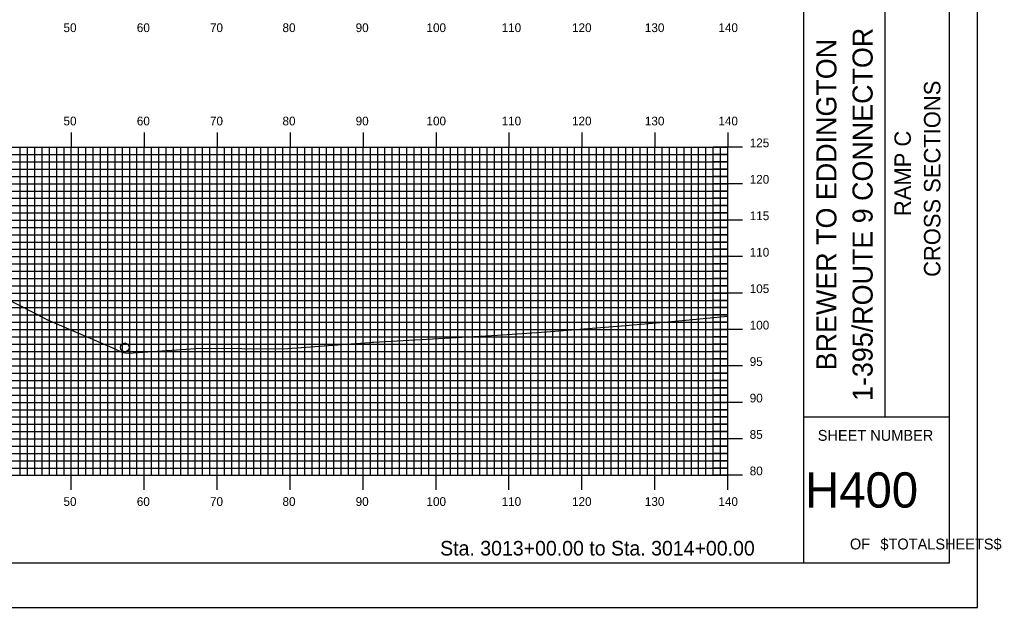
# Model space of a CAD drawing. Extents: x 1684405 to 1684749, y 461260 to 461480.
# Drawn here: x 1684614.1 to 1684748.7, y 461260 to 461340.6 of the extents above; entities that cross this region are included whole.
import ezdxf

# ---------------------------------------------------------------- set-up
doc = ezdxf.new("R2010")
doc.units = 0
for name, color, linetype in [('BORDER', 7, 'Continuous'), ('H_V ANNOTATION', 7, 'Continuous'), ('MAJOR', 7, 'Continuous'), ('MINOR', 7, 'Continuous'), ('PLOT BOUNDARY', 7, 'Continuous'), ('S_Drainage_Invert', 7, 'Continuous'), ('S_Roadway_Centerline', 7, 'Continuous')]:
    doc.layers.add(name, color=color, linetype=linetype)

msp = doc.modelspace()

# ---------------------------------------------------------------- linework, layer by layer
at = {"layer": 'BORDER'}
for p, q in [((1684721.6, 461266.07), (1684721.6, 461476.07)), ((1684732.79, 461286.08), (1684732.79, 461356.08)), ((1684721.6, 461286.08), (1684741.6, 461286.08))]:
    msp.add_line(p, q, dxfattribs=at)
msp.add_lwpolyline([(1684421.6, 461266.07), (1684741.6, 461266.07), (1684741.6, 461476.07), (1684421.6, 461476.07)], close=True, dxfattribs=at)
at = {"layer": 'MAJOR'}
for p, q in [((1684621.2, 461325.08), (1684621.2, 461323.07)), ((1684631.2, 461325.08), (1684631.2, 461323.07)), ((1684641.2, 461325.08), (1684641.2, 461323.07)), ((1684651.2, 461325.08), (1684651.2, 461323.07)), ((1684661.2, 461325.08), (1684661.2, 461323.07)), ((1684671.2, 461325.08), (1684671.2, 461323.07)), ((1684681.2, 461325.08), (1684681.2, 461323.07)), ((1684691.2, 461325.08), (1684691.2, 461323.07)), ((1684701.2, 461325.08), (1684701.2, 461323.07)), ((1684711.2, 461325.08), (1684711.2, 461323.07)), ((1684431.2, 461323.07), (1684711.2, 461323.07)), ((1684431.2, 461323.07), (1684711.2, 461323.07)), ((1684621.2, 461278.07), (1684621.2, 461323.07)), ((1684631.2, 461278.07), (1684631.2, 461323.07)), ((1684641.2, 461278.07), (1684641.2, 461323.07)), ((1684651.2, 461278.07), (1684651.2, 461323.07)), ((1684661.2, 461278.07), (1684661.2, 461323.07)), ((1684671.2, 461278.07), (1684671.2, 461323.07)), ((1684681.2, 461278.07), (1684681.2, 461323.07)), ((1684691.2, 461278.07), (1684691.2, 461323.07)), ((1684701.2, 461278.07), (1684701.2, 461323.07)), ((1684713.21, 461323.07), (1684709.2, 461323.07)), ((1684711.2, 461278.07), (1684711.2, 461323.07)), ((1684711.2, 461278.07), (1684711.2, 461323.07)), ((1684431.2, 461318.07), (1684711.2, 461318.07)), ((1684713.21, 461318.07), (1684709.2, 461318.07)), ((1684431.2, 461313.07), (1684711.2, 461313.07)), ((1684713.21, 461313.07), (1684709.2, 461313.07)), ((1684431.2, 461308.07), (1684711.2, 461308.07)), ((1684713.21, 461308.07), (1684709.2, 461308.07)), ((1684431.2, 461303.07), (1684711.2, 461303.07)), ((1684713.21, 461303.07), (1684709.2, 461303.07)), ((1684431.2, 461298.07), (1684711.2, 461298.07)), ((1684713.21, 461298.07), (1684709.2, 461298.07)), ((1684431.2, 461293.07), (1684711.2, 461293.07)), ((1684713.21, 461293.07), (1684709.2, 461293.07)), ((1684431.2, 461288.07), (1684711.2, 461288.07)), ((1684713.21, 461288.07), (1684709.2, 461288.07)), ((1684431.2, 461283.07), (1684711.2, 461283.07)), ((1684713.21, 461283.07), (1684709.2, 461283.07)), ((1684431.2, 461278.07), (1684711.2, 461278.07)), ((1684431.2, 461278.07), (1684711.2, 461278.07)), ((1684621.2, 461276.07), (1684621.2, 461278.07)), ((1684631.2, 461276.07), (1684631.2, 461278.07)), ((1684641.2, 461276.07), (1684641.2, 461278.07)), ((1684651.2, 461276.07), (1684651.2, 461278.07)), ((1684661.2, 461276.07), (1684661.2, 461278.07)), ((1684671.2, 461276.07), (1684671.2, 461278.07)), ((1684681.2, 461276.07), (1684681.2, 461278.07)), ((1684691.2, 461276.07), (1684691.2, 461278.07)), ((1684701.2, 461276.07), (1684701.2, 461278.07)), ((1684713.21, 461278.07), (1684709.2, 461278.07)), ((1684711.2, 461276.07), (1684711.2, 461278.07))]:
    msp.add_line(p, q, dxfattribs=at)
at = {"layer": 'MINOR'}
for p, q in [((1684431.2, 461322.07), (1684711.2, 461322.07)), ((1684614.2, 461278.07), (1684614.2, 461323.07)), ((1684615.2, 461278.07), (1684615.2, 461323.07)), ((1684616.2, 461278.07), (1684616.2, 461323.07)), ((1684617.2, 461278.07), (1684617.2, 461323.07)), ((1684618.2, 461278.07), (1684618.2, 461323.07)), ((1684619.2, 461278.07), (1684619.2, 461323.07)), ((1684620.2, 461278.07), (1684620.2, 461323.07)), ((1684622.2, 461278.07), (1684622.2, 461323.07)), ((1684623.2, 461278.07), (1684623.2, 461323.07)), ((1684624.2, 461278.07), (1684624.2, 461323.07)), ((1684625.2, 461278.07), (1684625.2, 461323.07)), ((1684626.2, 461278.07), (1684626.2, 461323.07)), ((1684627.2, 461278.07), (1684627.2, 461323.07)), ((1684628.2, 461278.07), (1684628.2, 461323.07)), ((1684629.2, 461278.07), (1684629.2, 461323.07)), ((1684630.2, 461278.07), (1684630.2, 461323.07)), ((1684632.2, 461278.07), (1684632.2, 461323.07)), ((1684633.2, 461278.07), (1684633.2, 461323.07)), ((1684634.2, 461278.07), (1684634.2, 461323.07)), ((1684635.2, 461278.07), (1684635.2, 461323.07)), ((1684636.2, 461278.07), (1684636.2, 461323.07)), ((1684637.2, 461278.07), (1684637.2, 461323.07)), ((1684638.2, 461278.07), (1684638.2, 461323.07)), ((1684639.2, 461278.07), (1684639.2, 461323.07)), ((1684640.2, 461278.07), (1684640.2, 461323.07)), ((1684642.2, 461278.07), (1684642.2, 461323.07)), ((1684643.2, 461278.07), (1684643.2, 461323.07)), ((1684644.2, 461278.07), (1684644.2, 461323.07)), ((1684645.2, 461278.07), (1684645.2, 461323.07)), ((1684646.2, 461278.07), (1684646.2, 461323.07)), ((1684647.2, 461278.07), (1684647.2, 461323.07)), ((1684648.2, 461278.07), (1684648.2, 461323.07)), ((1684649.2, 461278.07), (1684649.2, 461323.07)), ((1684650.2, 461278.07), (1684650.2, 461323.07)), ((1684652.2, 461278.07), (1684652.2, 461323.07)), ((1684653.2, 461278.07), (1684653.2, 461323.07)), ((1684654.2, 461278.07), (1684654.2, 461323.07)), ((1684655.2, 461278.07), (1684655.2, 461323.07)), ((1684656.2, 461278.07), (1684656.2, 461323.07)), ((1684657.2, 461278.07), (1684657.2, 461323.07)), ((1684658.2, 461278.07), (1684658.2, 461323.07)), ((1684659.2, 461278.07), (1684659.2, 461323.07)), ((1684660.2, 461278.07), (1684660.2, 461323.07)), ((1684662.2, 461278.07), (1684662.2, 461323.07)), ((1684663.2, 461278.07), (1684663.2, 461323.07)), ((1684664.2, 461278.07), (1684664.2, 461323.07)), ((1684665.2, 461278.07), (1684665.2, 461323.07)), ((1684666.2, 461278.07), (1684666.2, 461323.07)), ((1684667.2, 461278.07), (1684667.2, 461323.07)), ((1684668.2, 461278.07), (1684668.2, 461323.07)), ((1684669.2, 461278.07), (1684669.2, 461323.07)), ((1684670.2, 461278.07), (1684670.2, 461323.07)), ((1684672.2, 461278.07), (1684672.2, 461323.07)), ((1684673.2, 461278.07), (1684673.2, 461323.07)), ((1684674.2, 461278.07), (1684674.2, 461323.07)), ((1684675.2, 461278.07), (1684675.2, 461323.07)), ((1684676.2, 461278.07), (1684676.2, 461323.07)), ((1684677.2, 461278.07), (1684677.2, 461323.07)), ((1684678.2, 461278.07), (1684678.2, 461323.07)), ((1684679.2, 461278.07), (1684679.2, 461323.07)), ((1684680.2, 461278.07), (1684680.2, 461323.07)), ((1684682.2, 461278.07), (1684682.2, 461323.07)), ((1684683.2, 461278.07), (1684683.2, 461323.07)), ((1684684.2, 461278.07), (1684684.2, 461323.07)), ((1684685.2, 461278.07), (1684685.2, 461323.07)), ((1684686.2, 461278.07), (1684686.2, 461323.07)), ((1684687.2, 461278.07), (1684687.2, 461323.07)), ((1684688.2, 461278.07), (1684688.2, 461323.07)), ((1684689.2, 461278.07), (1684689.2, 461323.07)), ((1684690.2, 461278.07), (1684690.2, 461323.07)), ((1684692.2, 461278.07), (1684692.2, 461323.07)), ((1684693.2, 461278.07), (1684693.2, 461323.07)), ((1684694.2, 461278.07), (1684694.2, 461323.07)), ((1684695.2, 461278.07), (1684695.2, 461323.07)), ((1684696.2, 461278.07), (1684696.2, 461323.07)), ((1684697.2, 461278.07), (1684697.2, 461323.07)), ((1684698.2, 461278.07), (1684698.2, 461323.07)), ((1684699.2, 461278.07), (1684699.2, 461323.07)), ((1684700.2, 461278.07), (1684700.2, 461323.07)), ((1684702.2, 461278.07), (1684702.2, 461323.07)), ((1684703.2, 461278.07), (1684703.2, 461323.07)), ((1684704.2, 461278.07), (1684704.2, 461323.07)), ((1684705.2, 461278.07), (1684705.2, 461323.07)), ((1684706.2, 461278.07), (1684706.2, 461323.07)), ((1684707.2, 461278.07), (1684707.2, 461323.07)), ((1684708.2, 461278.07), (1684708.2, 461323.07)), ((1684709.2, 461278.07), (1684709.2, 461323.07)), ((1684711.2, 461322.07), (1684709.2, 461322.07)), ((1684710.2, 461278.07), (1684710.2, 461323.07)), ((1684431.2, 461321.07), (1684711.2, 461321.07)), ((1684711.2, 461321.07), (1684709.2, 461321.07)), ((1684431.2, 461320.07), (1684711.2, 461320.07)), ((1684431.2, 461319.07), (1684711.2, 461319.07)), ((1684711.2, 461320.07), (1684709.2, 461320.07)), ((1684711.2, 461319.07), (1684709.2, 461319.07)), ((1684431.2, 461317.07), (1684711.2, 461317.07)), ((1684711.2, 461317.07), (1684709.2, 461317.07)), ((1684431.2, 461316.07), (1684711.2, 461316.07)), ((1684431.2, 461315.07), (1684711.2, 461315.07)), ((1684711.2, 461316.07), (1684709.2, 461316.07)), ((1684711.2, 461315.07), (1684709.2, 461315.07)), ((1684431.2, 461314.07), (1684711.2, 461314.07)), ((1684711.2, 461314.07), (1684709.2, 461314.07)), ((1684431.2, 461312.07), (1684711.2, 461312.07)), ((1684431.2, 461311.07), (1684711.2, 461311.07)), ((1684711.2, 461312.07), (1684709.2, 461312.07)), ((1684711.2, 461311.07), (1684709.2, 461311.07)), ((1684431.2, 461310.07), (1684711.2, 461310.07)), ((1684711.2, 461310.07), (1684709.2, 461310.07)), ((1684431.2, 461309.07), (1684711.2, 461309.07)), ((1684711.2, 461309.07), (1684709.2, 461309.07)), ((1684431.2, 461307.07), (1684711.2, 461307.07)), ((1684711.2, 461307.07), (1684709.2, 461307.07)), ((1684431.2, 461306.07), (1684711.2, 461306.07)), ((1684711.2, 461306.07), (1684709.2, 461306.07)), ((1684431.2, 461305.07), (1684711.2, 461305.07)), ((1684711.2, 461305.07), (1684709.2, 461305.07)), ((1684431.2, 461304.07), (1684711.2, 461304.07)), ((1684711.2, 461304.07), (1684709.2, 461304.07)), ((1684431.2, 461302.07), (1684711.2, 461302.07)), ((1684711.2, 461302.07), (1684709.2, 461302.07)), ((1684431.2, 461301.07), (1684711.2, 461301.07)), ((1684711.2, 461301.07), (1684709.2, 461301.07)), ((1684431.2, 461300.07), (1684711.2, 461300.07)), ((1684431.2, 461299.07), (1684711.2, 461299.07)), ((1684711.2, 461300.07), (1684709.2, 461300.07)), ((1684711.2, 461299.07), (1684709.2, 461299.07)), ((1684431.2, 461297.07), (1684711.2, 461297.07)), ((1684711.2, 461297.07), (1684709.2, 461297.07)), ((1684431.2, 461296.07), (1684711.2, 461296.07)), ((1684431.2, 461295.07), (1684711.2, 461295.07)), ((1684711.2, 461296.07), (1684709.2, 461296.07)), ((1684711.2, 461295.07), (1684709.2, 461295.07)), ((1684431.2, 461294.07), (1684711.2, 461294.07)), ((1684711.2, 461294.07), (1684709.2, 461294.07)), ((1684431.2, 461292.07), (1684711.2, 461292.07)), ((1684431.2, 461291.07), (1684711.2, 461291.07)), ((1684711.2, 461292.07), (1684709.2, 461292.07)), ((1684711.2, 461291.07), (1684709.2, 461291.07)), ((1684431.2, 461290.07), (1684711.2, 461290.07)), ((1684711.2, 461290.07), (1684709.2, 461290.07)), ((1684431.2, 461289.07), (1684711.2, 461289.07)), ((1684711.2, 461289.07), (1684709.2, 461289.07)), ((1684431.2, 461287.07), (1684711.2, 461287.07)), ((1684711.2, 461287.07), (1684709.2, 461287.07)), ((1684431.2, 461286.07), (1684711.2, 461286.07)), ((1684711.2, 461286.07), (1684709.2, 461286.07)), ((1684431.2, 461285.07), (1684711.2, 461285.07)), ((1684431.2, 461284.07), (1684711.2, 461284.07)), ((1684711.2, 461285.07), (1684709.2, 461285.07)), ((1684711.2, 461284.07), (1684709.2, 461284.07)), ((1684431.2, 461282.07), (1684711.2, 461282.07)), ((1684711.2, 461282.07), (1684709.2, 461282.07)), ((1684431.2, 461281.07), (1684711.2, 461281.07)), ((1684431.2, 461280.07), (1684711.2, 461280.07)), ((1684711.2, 461281.07), (1684709.2, 461281.07)), ((1684711.2, 461280.07), (1684709.2, 461280.07)), ((1684431.2, 461279.07), (1684711.2, 461279.07)), ((1684711.2, 461279.07), (1684709.2, 461279.07))]:
    msp.add_line(p, q, dxfattribs=at)
at = {"layer": 'PLOT BOUNDARY'}
msp.add_lwpolyline([(1684405.42, 461259.95), (1684745.42, 461259.95), (1684745.42, 461479.95), (1684405.42, 461479.95)], close=True, dxfattribs=at)
at = {"layer": 'S_Drainage_Invert'}
msp.add_circle((1684628.53, 461295.62), 0.6, dxfattribs=at)
at = {"layer": 'S_Roadway_Centerline'}
msp.add_lwpolyline([(1684610.5, 461303.19), (1684616.37, 461300.2), (1684617.92, 461299.4), (1684627.06, 461295.47), (1684628.21, 461294.93), (1684629.06, 461294.81), (1684638.9, 461295.5), (1684650.22, 461295.41), (1684662.07, 461296.3), (1684662.45, 461296.33), (1684662.61, 461296.34), (1684679.63, 461297.29), (1684686.35, 461297.76), (1684697.16, 461298.64), (1684703.49, 461299.18), (1684711.2, 461299.9)], dxfattribs=at)

# ---------------------------------------------------------------- texts
at = {"layer": 'BORDER'}
for s, height, p in [('1-395/ROUTE 9 CONNECTOR', 2.7557, (1684731.05, 461288.27)), ('BREWER TO EDDINGTON', 2.7557, (1684726.09, 461292.48)), ('CROSS SECTIONS', 2.25, (1684740.34, 461305.29)), ('RAMP C', 2.25, (1684736.29, 461313.63))]:
    msp.add_text(s, height=height, rotation=90, dxfattribs=at).set_placement(p)
for s, height, p in [('SHEET NUMBER', 1.4905, (1684723.53, 461282.8)), ('H400', 4.839, (1684721.81, 461273.64)), ('OF', 1.491, (1684727.94, 461267.9)), ('$TOTALSHEETS$', 1.4905, (1684732.12, 461267.9))]:
    msp.add_text(s, height=height, dxfattribs=at).set_placement(p)
at = {"layer": 'H_V ANNOTATION'}
for s, height, p in [('50', 1.2, (1684620.13, 461338.87)), ('60', 1.2, (1684630.18, 461338.87)), ('70', 1.2, (1684640.21, 461338.87)), ('80', 1.2, (1684650.15, 461338.87)), ('90', 1.2, (1684660.18, 461338.87)), ('100', 1.2, (1684669.89, 461338.87)), ('110', 1.2, (1684680.19, 461338.87)), ('120', 1.2, (1684689.84, 461338.87)), ('130', 1.2, (1684699.83, 461338.87)), ('140', 1.2, (1684709.91, 461338.87)), ('50', 1.2, (1684620.13, 461326.07)), ('60', 1.2, (1684630.18, 461326.07)), ('70', 1.2, (1684640.21, 461326.07)), ('80', 1.2, (1684650.15, 461326.07)), ('90', 1.2, (1684660.18, 461326.07)), ('100', 1.2, (1684669.89, 461326.07)), ('110', 1.2, (1684680.19, 461326.07)), ('120', 1.2, (1684689.84, 461326.07)), ('130', 1.2, (1684699.83, 461326.07)), ('140', 1.2, (1684709.91, 461326.07)), ('125', 1.2, (1684714.2, 461323.07)), ('120', 1.2, (1684714.2, 461318.07)), ('115', 1.2, (1684714.2, 461313.07)), ('110', 1.2, (1684714.2, 461308.07)), ('105', 1.2, (1684714.2, 461303.07)), ('100', 1.2, (1684714.2, 461298.07)), ('95', 1.2, (1684714.2, 461293.07)), ('90', 1.2, (1684714.2, 461288.07)), ('85', 1.2, (1684714.2, 461283.07)), ('80', 1.2, (1684714.2, 461278.07)), ('50', 1.2, (1684620.13, 461273.87)), ('60', 1.2, (1684630.18, 461273.87)), ('70', 1.2, (1684640.21, 461273.87)), ('80', 1.2, (1684650.15, 461273.87)), ('90', 1.2, (1684660.18, 461273.87)), ('100', 1.2, (1684669.89, 461273.87)), ('110', 1.2, (1684680.19, 461273.87)), ('120', 1.2, (1684689.84, 461273.87)), ('130', 1.2, (1684699.83, 461273.87)), ('140', 1.2, (1684709.91, 461273.87)), ('Sta. 3013+00.00 to Sta. 3014+00.00', 2.0004, (1684671.76, 461267.07))]:
    msp.add_text(s, height=height, dxfattribs=at).set_placement(p)

doc.saveas('drawing.dxf')
